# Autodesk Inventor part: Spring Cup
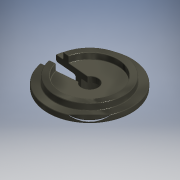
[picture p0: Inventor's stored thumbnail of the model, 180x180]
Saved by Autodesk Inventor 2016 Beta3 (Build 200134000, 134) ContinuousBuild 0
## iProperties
Shininess: 50.0
Compacted: True
Length Units: 11272
Angle Units: 11279
Time Units: 11290
Mass Units: 11286
Length Display Precision: 4
Angle Display Precision: 2
Company: Autodesk
Created: 2000-03
Part Number: Spring Cup
Project: Inventor Samples
User Status: IN PROGRESS
Document SubType Name: Modeling
Designer: Autodesk, Inc.
Density: 1.13 g/cm^3
Mass: 0.4348 g
Surface Area: 6.80342 cm^2
Volume: 0.384779 cm^3
Material: Nylon-6/6
Appearance: Gunmetal
Density: 0.0
Volumn: 0.0
Area: 0.0
PropertySet Name: Model Information
Control State: 0
Master: False
Checked Out: False
Author: Autodesk, Inc.
Revision Number: A
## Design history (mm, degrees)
node "Revolution1" dims "d10" = 90 deg
  sketch "Sketch2"
    geometry: L1 (-6.24, 5.709)-(-6.24, -3.546); L2 (-9.224, -2.438)-(-9.224, 0.102); L3 (-9.224, 0.102)-(-7.891, 0.102); L4 (-7.891, 0.102)-(-7.891, 1.372); L5 (-7.891, 1.372)-(-11.955, 1.372); L6 (-11.955, 1.372)-(-11.955, 2.642); L7 (-11.955, 2.642)-(-13.225, 2.642); L8 (-13.225, 2.642)-(-13.225, 1.372); L9 (-13.225, 1.372)-(-14.812, 1.372); L10 (-14.812, 1.372)-(-14.812, 0.102); L11 (-14.812, 0.102)-(-10.494, 0.102); L12 (-10.494, 0.102)-(-10.494, -2.438); L13 (-10.494, -2.438)-(-9.224, -2.438)
    constraints: 26 end point, 10 parallel, 3 collinear, 1 perpendicular, 1 vertical, 1 other
    dimensions: "d0" = 13.97 diameter of L8 L1; "d1" = 1.27 distance of L6.end L7.end; "d2" = 1.27 distance from line of L7.end L9; "d3" = 2.54 distance between parallel lines of L13 L11; "d4" = 3.302 diameter of L4 L1; "d5" = 5.969 diameter of L2 L1; "d6" = 1.27 distance between parallel lines of L2 L12; "d7" = 17.145 diameter of L10 L1; "d8" = 11.43 diameter of L6 L1; "d9" = 1.27 distance between parallel lines of L9 L11
node "Fillet1" dims "d11" = 0.381
node "Extrusion1" dims "d15" = 25.4, "d16" = 0
  sketch "Sketch3"
    geometry: L1 (0, 0)-(-10.431, 0); L2 (-8.572, 1.544)-(-8.572, -1.544); L3 (-8.572, -1.544)-(0, -0.794); L4 (-8.572, 1.544)-(0, 0.794); L5 (0, 0.794)-(0, -0.794); C1 r 1.651 at (0, 0) reference; C2 r 5.715 at (0, 0) reference; C3 r 8.572 at (0, 0) reference
    constraints: 10 end point, 1 equal length, 1 horizontal, 1 midpoint, 1 perpendicular, 1 tangent, 1 vertical
    dimensions: "d12" = 10 deg angle of L3 L4; "d13" = 1.5875 distance of L4.end L3.end; "d14" = 0.79375 distance of C1.centre L3.end (= 0.5 x d13)
node "Fillet2" dims "d17" = 0.127
node "Fillet3" dims "d18" = 0.127
body "Solid1"
